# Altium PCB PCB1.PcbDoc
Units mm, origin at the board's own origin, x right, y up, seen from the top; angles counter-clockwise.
Board outline 100 x 140 mm, 2 copper layers (Top Layer, Bottom Layer); 119 components, 80 nets, 399 pads, 0 vias.
Unrouted connection lines stored in the file: 245.
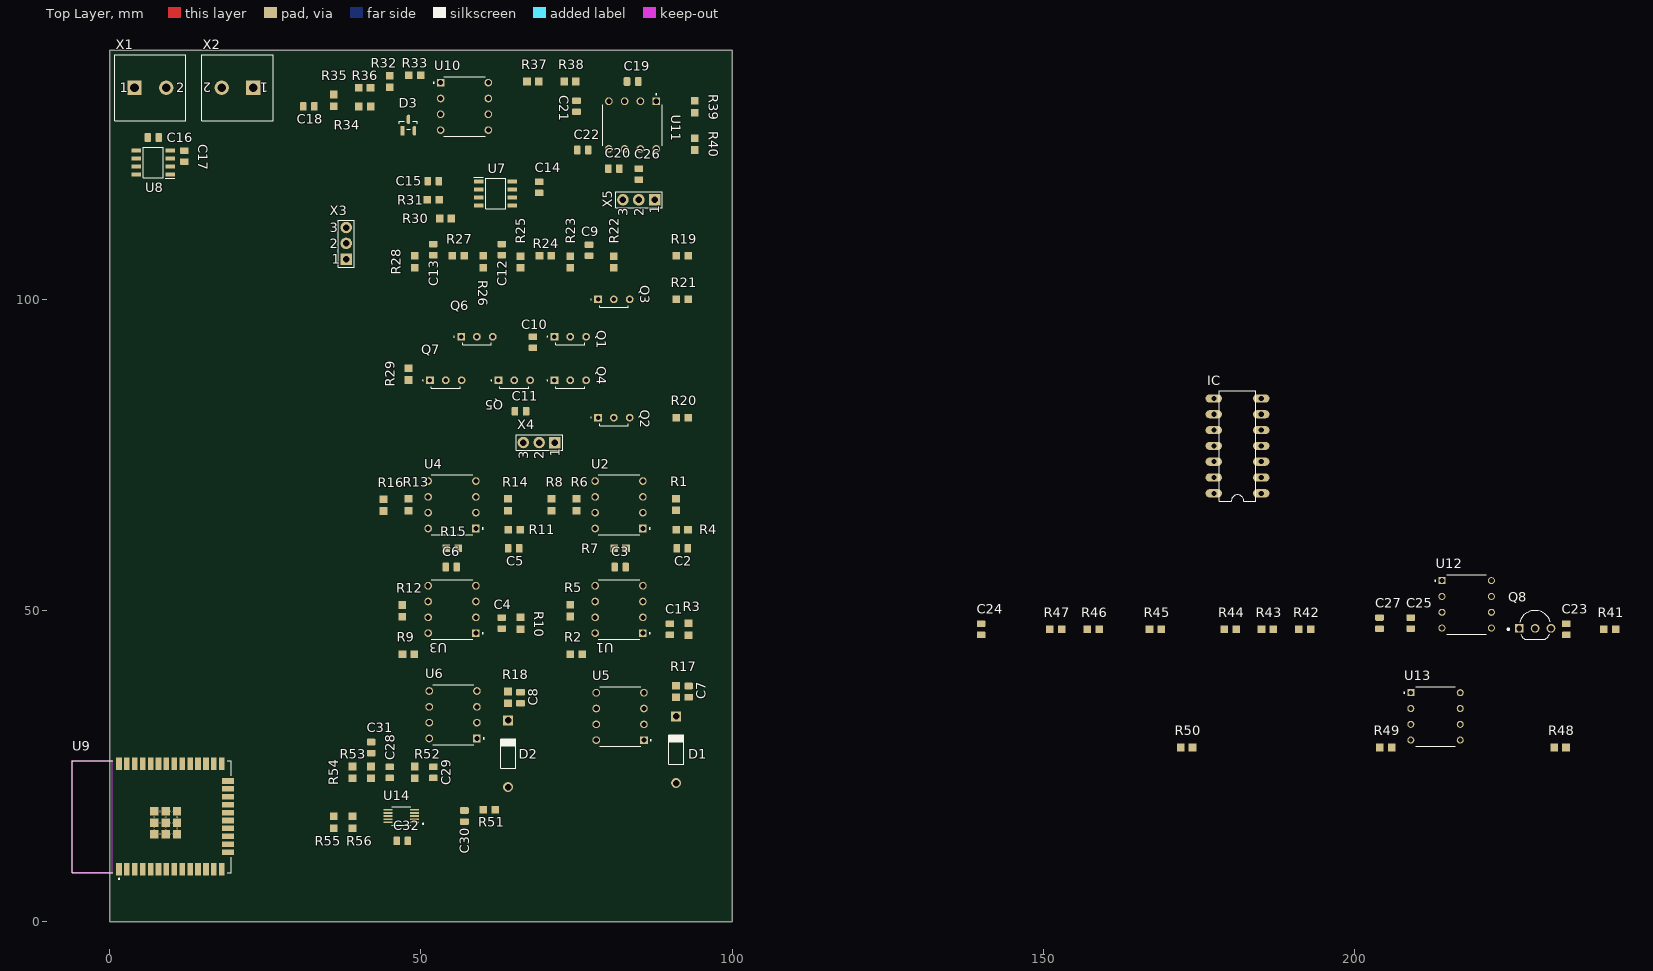
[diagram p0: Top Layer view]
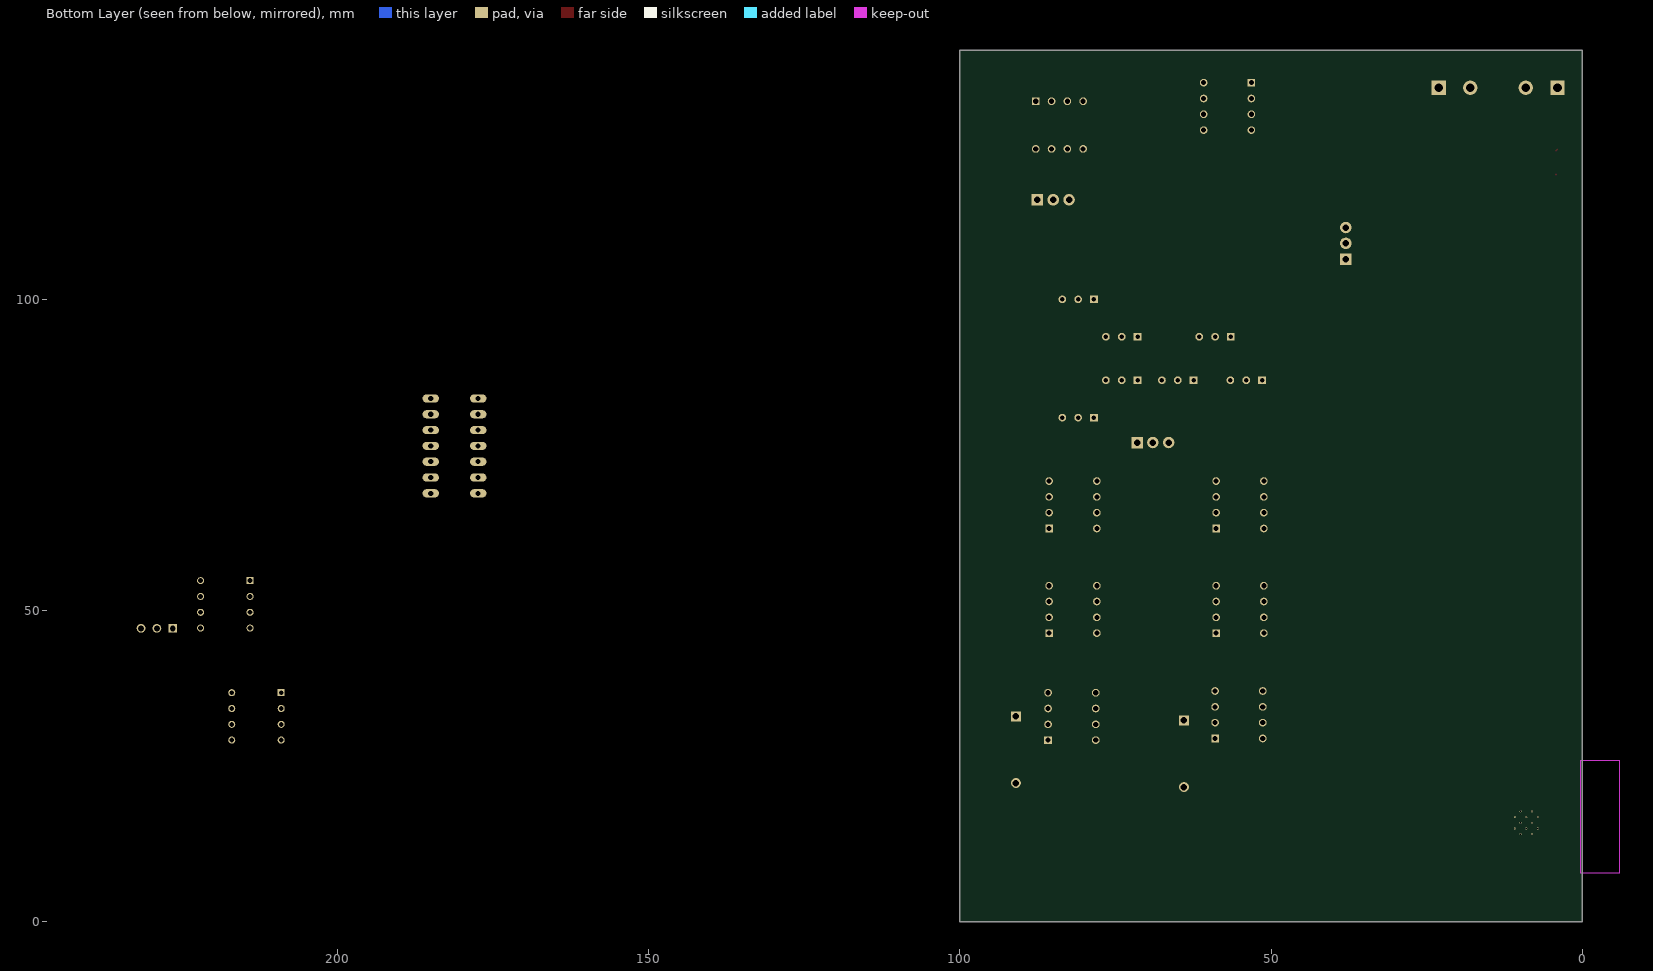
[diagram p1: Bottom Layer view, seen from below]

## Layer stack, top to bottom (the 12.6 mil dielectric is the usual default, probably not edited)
Top Solder: solder mask 0.0102, Solder Resist, Dk 3.5
Top Layer: signal copper 0.0356
Dielectric 1: dielectric 0.32, FR-4, Dk 4.8
Bottom Layer: signal copper 0.0356
Bottom Solder: solder mask 0.0102, Solder Resist, Dk 3.5

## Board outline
0,0 100,0 100,140 0,140

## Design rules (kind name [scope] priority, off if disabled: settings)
Clearance [All] p1: gap=0.254 ignorepadtopadclearanceinfootprint=FALSE
PolygonConnect [All] p1: connectstyle=Relief reliefconductorwidth=0.254 reliefentries=4 polygonreliefangle="90 Angle" airgapwidth=0.254
RoutingVias [All] p1: holewidth=0.711 width=1.27 viastyle="Through Hole" minholewidth=0.711 minwidth=1.27 maxholewidth=0.711 maxwidth=1.27
SolderMaskExpansion [All] p1: expansion=0 istentingtop=FALSE
SupplyNets "Schematic Supply Nets" [InNet('GND')] p1: voltage=0.000
Width [All] p1: maxlimit=0.254 minlimit=0.254 preferedwidth=0.254
30 further rules are at their usual default settings.

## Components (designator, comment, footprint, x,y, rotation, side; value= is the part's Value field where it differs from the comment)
C1 "100nF" CAPC2012X95N 90,47 r90 top
C2 "100nF" CAPC2012X95N 92,60 r180 top
C3 "100nF" CAPC2012X95N 82,57 r0 top
C4 "100nF" CAPC2012X95N 63,48 r90 top
C5 "100nF" CAPC2012X95N 64.888,60 r180 top
C6 "100nF" CAPC2012X95N 54.888,57 r180 top
C7 "100nF" CAPC2012X95N 93,37 r90 top
C8 "100nF" CAPC2012X95N 66,36 r90 top
C9 "100nF" CAPC2012X95N 77,107.888 r90 top
C10 "100nF" CAPC2012X95N 68,93.112 r270 top
C11 "100nF" CAPC2012X95N 66,82 r180 top
C12 "100nF" CAPC2012X95N 63,108 r90 top
C13 "100nF" CAPC2012X95N 52,108 r90 top
C14 "100nF" CAPC2012X95N 69,118 r270 top
C15 "100nF" CAPC2012X95N 52,119 r0 top
C16 "100nF" CAPC2012X95N 7,126 r0 top
C17 "100nF" CAPC2012X95N 12,123 r90 top
C18 "1nF" CAPC2012X95N 32,131 r180 top
C19 "1.2nF" CAPC2012X95N 84,135 r0 top
C20 "6.8nF" CAPC2012X95N 81,121 r0 top
C21 "1nF" CAPC2012X95N 75,131 r90 top
C22 "1nF" CAPC2012X95N 76,124 r0 top
C23 "100nF" CAPC2012X95N 234,47 r90 top
C24 "100nF" CAPC2012X95N 140,47 r90 top
C25 "100nF" CAPC2012X95N 209,48 r90 top
C26 "100nF" CAPC2012X95N 85,120.112 r90 top
C27 "100nF" CAPC2012X95N 204,48 r90 top
C28 "100pF" CAPC2012X95N 45,24 r90 top value=1nF
C29 "100pF" CAPC2012X95N 52,24 r90 top value=1nF
C30 "100pF" CAPC2012X95N 57,17 r270 top value=1nF
C31 "100nF" CAPC2012X95N 42,28 r270 top value=1nF
C32 "100nF" CAPC2012X95N 47,13 r180 top value=1nF
D1 "IN4007" DIOAD1070W78L470D235P 91,27.65 r270 top
D2 "IN4007" DIOAD1070W78L470D235P 64,27 r270 top
D3 "BAV99LT1G" FP-318-08-IPC_B 48,128 r90 top
IC "ICL8038" ICL8038 181.19,76.46 r90 top
Q1 "2N2222A" 2N2222A 71.46,94 r0 top
Q2 "2N2222A" 2N2222A 78.46,81 r0 top
Q3 "2N2222A" 2N2222A 78.46,100 r0 top
Q4 "2N2222A" 2N2222A 71.46,87 r0 top
Q5 "2N2222A" 2N2222A 62.46,87 r0 top
Q6 "2N2222A" 2N2222A 56.46,94 r0 top
Q7 "2N2222A" 2N2222A 51.46,87 r0 top
Q8 "2N3904TF" TO92254P520H877-3 229,48 r0 top
R1 "10k" RC0805N_YAG-M 91,67.048 r90 top
R2 "10k" RC0805N_YAG-M 74.953,43 r0 top
R3 "10k" RC0805N_YAG-M 93,47 r90 top
R4 "10k" RC0805N_YAG-M 91.953,63 r0 top
R5 "10k" RC0805N_YAG-M 74,50 r90 top
R6 "10k" RC0805N_YAG-M 75,67 r90 top
R7 "10k" RC0805N_YAG-M 82,60 r0 top
R8 "10k" RC0805N_YAG-M 71,67 r270 top
R9 "10k" RC0805N_YAG-M 48,43 r0 top
R10 "10k" RC0805N_YAG-M 66,47.953 r270 top
R11 "10k" RC0805N_YAG-M 65,63 r0 top
R12 "10k" RC0805N_YAG-M 47,49.953 r90 top
R13 "10k" RC0805N_YAG-M 48,67 r90 top
R14 "10k" RC0805N_YAG-M 64,67 r90 top
R15 "10k" RC0805N_YAG-M 55.048,60 r0 top
R16 "10k" RC0805N_YAG-M 44,66.953 r270 top
R17 "10k" RC0805N_YAG-M 91,37 r270 top
R18 "10k" RC0805N_YAG-M 64,36.048 r270 top
R19 "10k" RC0805N_YAG-M 92,107 r0 top
R20 "10k" RC0805N_YAG-M 92,81 r0 top
R21 "10k" RC0805N_YAG-M 92,100 r0 top
R22 "10k" RC0805N_YAG-M 81,106 r270 top
R23 "10k" RC0805N_YAG-M 74,106 r270 top
R24 "10k" RC0805N_YAG-M 70,107 r0 top
R25 "10k" RC0805N_YAG-M 66,106 r270 top
R26 "10k" RC0805N_YAG-M 60,106.048 r270 top
R27 "10k" RC0805N_YAG-M 56,107 r0 top
R28 "10k" RC0805N_YAG-M 49,106.048 r90 top
R29 "10k" RC0805N_YAG-M 48,88 r270 top
R30 "10k" RC0805N_YAG-M 53.953,113 r180 top
R31 "10k" RC0805N_YAG-M 52,116 r180 top
R32 "25k" RC0805N_YAG-M 45,135 r270 top
R33 "2.8k" RC0805N_YAG-M 49,136 r180 top
R34 "47.5k" RC0805N_YAG-M 41,131 r180 top
R35 "10M" RC0805N_YAG-M 36,131.953 r90 top
R36 "909" RC0805N_YAG-M 40.953,134 r180 top
R37 "29.4k" RC0805N_YAG-M 68,135 r180 top
R38 "29.4k" RC0805N_YAG-M 73.953,135 r180 top
R39 "12.4k" RC0805N_YAG-M 94,130.953 r90 top
R40 "12.4k" RC0805N_YAG-M 94,124.953 r90 top
R41 "10k" RC0805N_YAG-M 241,47 r0 top
R42 "10k" RC0805N_YAG-M 192,47 r0 top
R43 "10k" RC0805N_YAG-M 186,47 r0 top
R44 "10k" RC0805N_YAG-M 180,47 r0 top
R45 "10k" RC0805N_YAG-M 168,47 r0 top
R46 "10k" RC0805N_YAG-M 158,47 r0 top
R47 "10k" RC0805N_YAG-M 152,47 r0 top
R48 "10k" RC0805N_YAG-M 233,28 r0 top
R49 "10k" RC0805N_YAG-M 205,28 r0 top
R50 "10k" RC0805N_YAG-M 173,28 r0 top
R51 "1k" RC0805N_YAG-M 61,18 r0 top value=10k
R52 "1k" RC0805N_YAG-M 49,24 r90 top value=10k
R53 "1k" RC0805N_YAG-M 42,24 r90 top value=10k
R54 "10k" RC0805N_YAG-M 39,24 r90 top
R55 "4.7k" RC0805N_YAG-M 36,16 r90 top value=10k
R56 "4.7k" RC0805N_YAG-M 39,16 r90 top value=10k
U1 "NE5532N" DIP766W45P254L1016H533Q8 81.83,50.19 r180 top
U2 "NE5532N" DIP766W45P254L1016H533Q8 81.83,67 r180 top
U3 "NE5532N" DIP766W45P254L1016H533Q8 55,50.19 r180 top
U4 "NE5532N" DIP766W45P254L1016H533Q8 55,67 r180 top
U5 "NE5532N" DIP766W45P254L1016H533Q8 82,33 r180 top
U6 "NE5532N" DIP766W45P254L1016H533Q8 55.17,33.27 r180 top
U7 "AD633JRZ-R7" SOIC127P600X175-8N 62,117 r0 top
U8 "ICL7660SIBAZT" SOIC127P600X175-8N 7,122 r180 top
U9 "ESP32-WROOM-32D-N4" MODULE_ESP32-WROOM-32D-N4 6.76,16.917 r90 top
U10 "NE5532N" DIP766W45P254L1016H533Q8 57,131 r0 top
U11 "NE5532N" DIP766W45P254L1016H533Q8 84,128 r270 top
U12 "TL072CPE4" DIP794W45P254L959H508Q8 218,51 r0 top
U13 "TL072CPE4" DIP794W45P254L959H508Q8 213,33 r0 top
U14 "ADS1115IDGSR" SOP50P490X110-10N 46.85,17 r180 top
X1 "Terminal" CON_TERMINAL_2POL 4,134 r0 top value=10k
X2 "Terminal" CON_TERMINAL_2POL 23.08,134 r180 top value=10k
X3 "Jumper" CON_JUMPER_3POL 38,106.46 r0 top value=10k
X4 "Jumper" CON_JUMPER_3POL 71.54,77 r90 top value=10k
X5 "Jumper" CON_JUMPER_3POL 87.54,116 r90 top value=10k

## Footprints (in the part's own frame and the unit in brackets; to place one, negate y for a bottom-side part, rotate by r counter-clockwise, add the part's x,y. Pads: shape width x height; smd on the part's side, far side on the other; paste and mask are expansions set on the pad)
2N2222A [mm]
  rect 1.234x1.234 hole 0.72: 1(0,0)
  round 1.234 hole 0.72: 2(2.54,0) 3(5.08,0)
  silkscreen extent -1.2,-1.27 4.84,0.05, body extent -0.2,-1.25 5.28,2.35, height 7.46
CAPC2012X95N [mm]
  rrect25% 1.05x1.38 smd: 1(-0.888,0) 2(0.888,0)
  body extent -1,-0.63 1,0.63, height 0.95
CON_JUMPER_3POL [mm] "Jumper"
  rect 1.85x1.85 hole 1.05: 1(0,0)
  round 1.85 hole 1.05: 2(0,2.54) 2(0,5.08)
  silkscreen extent -1.27,-1.27 1.27,6.22
CON_TERMINAL_2POL [mm] "Terminal Screw"
  rect 2.3x2.3 hole 1.4: 1(0,0)
  round 2.3 hole 1.4: 2(5.08,0)
  silkscreen extent -3.17,-5.33 8.25,5.33
DIOAD1070W78L470D235P [mm]
  round 1.6 hole 1.05: A(5.35,0)
  rect 1.6x1.6 / inner round 1.6 / far side rect 1.6x1.6 hole 1.05: C(-5.35,0)
  silkscreen extent -2.4,-1.2 2.35,1.2, body extent -5.74,-1.35 5.74,1.35, height 2.7
DIP766W45P254L1016H533Q8 [mm]
  rect 1.23x1.23 / inner round 1.23 / far side rect 1.23x1.23 hole 0.82: 1(-3.83,3.81)
  round 1.23 hole 0.82: 2(-3.83,1.27) 3(-3.83,-1.27) 4(-3.83,-3.81) 5(3.83,-3.81) 6(3.83,-1.27) 7(3.83,1.27) 8(3.83,3.81)
  silkscreen extent -5.03,-4.79 3.3,4.79, body extent -4,-4.94 4,4.94, height 5.33
DIP794W45P254L959H508Q8 [mm]
  rect 1.13x1.13 / inner round 1.13 / far side rect 1.13x1.13 hole 0.78 mask+0.102: 1(-3.97,3.81)
  round 1.13 hole 0.78 mask+0.102: 2(-3.97,1.27) 3(-3.97,-1.27) 4(-3.97,-3.81) 5(3.97,-3.81) 6(3.97,-1.27) 7(3.97,1.27) 8(3.97,3.81)
  silkscreen extent -5.13,-4.79 3.17,4.79, body extent -4.1,-4.79 4.1,4.79, height 5.08
FP-318-08-IPC_B [mm]
  rect 1.524x0.578 smd paste+0 mask+0: 1(-0.91,0.95)
  rrect100% 1.524x0.578 smd paste+0 mask+0: 2(-0.91,-0.95) 3(0.91,0)
  silkscreen extent -0.65,-1.45 0.65,1.45, body extent -1.92,-1.7 1.92,1.7, height 0.25
ICL8038 [mil]
  oval 52x104 hole 32: 1(-300,-150) 2(-200,-150) 3(-100,-150) 4(0,-150) 5(100,-150) 6(200,-150) 7(300,-150) 8(300,150) 9(200,150) 10(100,150) 11(0,150) 12(-100,150) 13(-200,150) 14(-300,150)
  silkscreen extent -350,-115 350,115
MODULE_ESP32-WROOM-32D-N4 [mm]
  rect 2x0.9 smd: 1(-8.5,5.26) 2(-8.5,3.99) 3(-8.5,2.72) 4(-8.5,1.45) 5(-8.5,0.18) 6(-8.5,-1.09) 7(-8.5,-2.36) 8(-8.5,-3.63) 9(-8.5,-4.9) 10(-8.5,-6.17) 11(-8.5,-7.44) 12(-8.5,-8.71) 13(-8.5,-9.98) 14(-8.5,-11.25) 25(8.5,-11.25) 26(8.5,-9.98) 27(8.5,-8.71) 28(8.5,-7.44) 29(8.5,-6.17) 30(8.5,-4.9) 31(8.5,-3.63) 32(8.5,-2.36) 33(8.5,-1.09) 34(8.5,0.18) 35(8.5,1.45) 36(8.5,2.72) 37(8.5,3.99) 38(8.5,5.26)
  rect 0.9x2 smd: 15(-5.715,-12.25) 16(-4.445,-12.25) 17(-3.175,-12.25) 18(-1.905,-12.25) 19(-0.635,-12.25) 20(0.635,-12.25) 21(1.905,-12.25) 22(3.175,-12.25) 23(4.445,-12.25) 24(5.715,-12.25)
  rect 1.33x1.33 smd: 39_1(-2.835,-0.405) 39_2(-1,-0.405) 39_3(0.835,-0.405) 39_4(-2.835,-2.24) 39_5(-1,-2.24) 39_6(0.835,-2.24) 39_7(-2.835,-4.075) 39_8(-1,-4.075) 39_9(0.835,-4.075)
  round 0.3 hole 0.2: 39_10(-1.917,-0.405) 39_11(-0.082,-0.405) 39_12(-2.835,-1.322) 39_13(-1,-1.322) 39_14(0.835,-1.322) 39_15(-1.917,-2.24) 39_16(-0.082,-2.24) 39_17(-2.835,-3.157) 39_18(-1,-3.157) 39_19(0.835,-3.157) 39_20(-1.917,-4.075) 39_21(-0.082,-4.075)
  Keep-Out Layer region: 9,6.45 -9,6.45 -9,12.75 9,12.75
  silkscreen extent -10.1,-12.75 9,12.75, body extent -9,-12.75 9,12.75, height 3.25
RC0805N_YAG-M [mil]
  rect 48x49 smd paste+0 mask+0: 1(-37.5,0) 2(37.5,0)
  body extent -39,-24 39,24, height 28
SOIC127P600X175-8N [mm]
  rect 1.525x0.65 smd: 1(-2.712,1.905) 2(-2.712,0.635) 3(-2.712,-0.635) 4(-2.712,-1.905) 5(2.712,-1.905) 6(2.712,-0.635) 7(2.712,0.635) 8(2.712,1.905)
  silkscreen extent -3.47,-2.45 1.6,2.58, body extent -3,-2.45 3,2.45, height 1.75
SOP50P490X110-10N [mm]
  rrect25% 1.47x0.28 smd: 1(-2.15,1) 2(-2.15,0.5) 3(-2.15,0) 4(-2.15,-0.5) 5(-2.15,-1) 6(2.15,-1) 7(2.15,-0.5) 8(2.15,0) 9(2.15,0.5) 10(2.15,1)
  silkscreen extent -3.6,-1.5 1.5,1.5, body extent -2.45,-1.5 2.45,1.5, height 1.1
TO92254P520H877-3 [mm]
  rect 1.41x1.41 / inner round 1.41 / far side rect 1.41x1.41 hole 0.94: 1(-2.54,-0.853)
  round 1.41 hole 0.94: 2(0,-0.853) 3(2.54,-0.853)
  silkscreen extent -4.44,-2.62 2.47,2.01, body extent -2.83,-1.43 2.83,2.19, height 8.77

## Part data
C1 C2 C3 C4 C5 C6 C7 C8 C9 C10 C11 C12 C13 C14 C15 C16 C17 C18 C19 C20 C21 C22 C23 C24 C25 C26 C27 C28 C29 C30 C31 C32: library part CAP_0805_GENERIC, "0.1 ÂµF Â±10% 50V Ceramic Capacitor X7R 0805 (2012 Metric)", Package="SMD-2 Samsung", Voltage=50V
D1 D2: "Diode Standard 1000 V 1A Through Hole DO-204AL (DO-41)", Package="DO-41 Vishay Semiconductor"
D3: library part CMP-07163-000036-1, "DIODE ARRAY 100V 215MA SOT23-3", Capacitance=1.5pF, Case/Package=SOT-23, Current Rating=200mA, Forward Current=150mA, Forward Voltage=1.25V, Max Forward Surge Current (Ifsm)=500mA, Max Operating Temperature=150°C, Max Repetitive Reverse Voltage (Vrrm)=70V, Min Operating Temperature=-65°C, Peak Non-Repetitive Surge Current=2A, Peak Reverse Current=2.5uA
IC: "IC OSCILL GEN/VOLT CONTROL 14DIP", Package=None
Q1 Q2 Q3 Q4 Q5 Q6 Q7: "Transistor BJT NPN", Manufacturer_Name=Diotec, Mouser Part Number=637-2N2222A
Q8: "Transistor General Purpose BJT NPN 40 Volt 0.2 Amp 3-Pin TO-92 Tape And Reel", Package="TO-92-3 ON Semiconductor"
R1 R2 R3 R4 R5 R6 R7 R8 R9 R10 R11 R12 R13 R14 R15 R16 R17 R18 R19 R20 R21 R22 R23 R24 R25 R26 R27 R28 R29 R30 R31 R32 R33 R34 R35 R36 R37 R38 R39 R40 R41 R42 R43 R44 R45 R46 R47 R48 R49 R50 R51 R52 R53 R54 R55 R56: library part RES_0805_GENERIC_1, "Description", Manufacturer_Name=Yageo, Manufacturer_Part_Number=RC0805FR-0710KL
U1 U2 U3 U4 U5 U6 U10 U11: "IC, OP AMP, DUAL; No. of Amplifiers: 2 Amplifier; Bandwidth: 10MHz; Slew Rate: 8V/Âµs; Supply Voltage Range: Â± 15V; Amplifier Case Style: DIP; No. of Pins: 8Pins; Operating Temperature Min: 0Â°C; Operating Temperature Max: 70Â°C; MSL: -; SVHC: No SVHC (1", Package="PDIP-8 ON Semiconductor"
U7: "Analog Multiplier 4-Quadrant 8-SOIC", Package="SOIC-8 Analog Devices"
U8: "Charge Pump Switching Regulator IC Positive or Negative Fixed -Vin, 2Vin 1 Output 45mA 8-SOIC (0.154, 3.90mm Width)", Package="SOIC-8 Renesas Electronics America Inc"
U9: "Bluetooth, WiFi 802.11b/g/n, Bluetooth v4.2 +EDR, Class 1, 2 and 3 Transceiver Module 2.4GHz ~ 2.5GHz Integrated, Trace Surface Mount", Package="Non Standard Espressif Systems"
U12 U13: "Dual Low-Noise JFET-Input General-Purpose Operational Amplifier 8-PDIP 0 to 70", Package="PDIP-8 Texas"
U14: "16-bit, 860-SPS, 4-channel, delta-sigma ADC with PGA, oscillator, VREF, comparator and I2C", Package="VSSOP-10 Texas Instruments"
X1 X2: library part CON_TERMINAL_2POL, "Terminal Screw", Manufacturer_Name=Yageo, Manufacturer_Part_Number=RC0805FR-0710KL
X3 X4 X5: library part CON_JUMPER_3POL, Manufacturer_Name=Yageo, Manufacturer_Part_Number=RC0805FR-0710KL

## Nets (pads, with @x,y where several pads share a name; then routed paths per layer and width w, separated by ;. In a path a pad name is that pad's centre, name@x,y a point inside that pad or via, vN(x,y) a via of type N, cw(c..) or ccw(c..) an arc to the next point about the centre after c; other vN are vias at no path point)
GND: C7.2 C8.2 C9.2 C10.1 C11.1 C12.2 C13.2 C14.1 C15.1 C16.2 C21.1 C22.1 C28.2 C29.2 C30.2 C32.1 R17.1 R18.1 R28.1 R29.1 R31.2 R35.2 R36.2 R54.2 U1.3 U1.5 U2.3 U2.5 U3.3 U3.5 U4.3 U4.5 U7.2 U7.8 U8.3 U13.3 U14.1 U14.3 X1.2 X2.2
NetC1_1: C1.1 R3.1 U1.1
NetC1_2: C1.2 R2.2 U1.2
NetC2_1: C2.1 R1.1 R3.2 R4.2 U2.2
NetC2_2: C2.2 C3.1 R4.1 R7.2 U2.1
NetC3_2: C3.2 R5.2 R7.1 U1.6
NetC4_1: C4.1 R10.1 U3.1
NetC4_2: C4.2 R9.2 U3.2
NetC5_1: C5.1 R10.2 R11.2 R14.1 U4.2
NetC5_2: C5.2 C6.1 R11.1 R15.2 U4.1
NetC6_2: C6.2 R12.2 R15.1 U3.6
NetC7_1: C7.1 D1.C R17.2 U5.2 U5.5
NetC8_1: C8.1 D2.C R18.2 U6.2 U6.5
NetC9_1: C9.1 R19.1 R22.1 R23.1 R24.2
NetC10_2: C10.2 Q1.2 Q4.2 R23.2
NetC11_2: C11.2 Q5.2 R25.2
NetC12_1: C12.1 R24.1 R25.1 R26.1 R27.2
NetC13_1: C13.1 Q7.2 R27.1 R28.2
NetC14_2: C14.2 C32.2 D3.2 IC.6 R19.2 R20.2 R21.2 R45.2 R47.2 R55.2 R56.2 U1.8 U2.8 U3.8 U4.8 U5.8 U6.8 U7.6 U8.8 U10.8 U11.8 U12.8 U13.8 U14.8 X1.1 | length 0.1
  Top Layer w0.254: U8.8@4.193,120 U8.8
NetC15_2: C15.2 C16.1 C24.2 D3.1 IC.11 R46.1 R50.1 U1.4 U2.4 U3.4 U4.4 U5.4 U6.4 U7.3 U8.5 U10.4 U11.4 U12.4 U13.4 | length 0.4
  Top Layer w0.254: U8.5@4,124.103 4.198,123.905 U8.5
NetC17_1: C17.1 U8.2
NetC17_2: C17.2 U8.4
NetC18_1: C18.1 R34.2 R35.1
NetC18_2: C18.2 X2.1
NetC19_1: C19.1 C21.2 R38.1 U11.3
NetC19_2: C19.2 R39.2 U11.1 U11.2
NetC20_1: C20.1 C22.2 R40.1 U11.5
NetC20_2: C20.2 C26.2 U11.6 U11.7
NetC23_1: C23.1 Q8.1 R42.1 U12.2
NetC23_2: C23.2 C31.1 IC.8 Q8.3 R44.1 U12.1
NetC24_1: C24.1 IC.10
NetC25_1: C25.1 X3.2
NetC25_2: C25.2 R48.1 U13.1
NetC26_1: C26.1 X5.2
NetC27_1: C27.1 X4.2
NetC27_2: C27.2 R1.2 R14.2
NetC28_1: C28.1 R53.1 U14.6
NetC29_1: C29.1 R52.1 U14.5
NetC30_1: C30.1 R51.1 U14.4
NetC31_2: C31.2 R53.2
NetD1_A: D1.A U5.1
NetD2_A: D2.A U6.1
NetD3_3: D3.3 R34.1 U10.3
NetIC_3: IC.3 R49.2
NetIC_4: IC.4 R45.1
NetIC_5: IC.5 R47.1
NetIC_12: IC.12 R46.2
NetQ1_1: Q1.1 Q3.1 Q6.3
NetQ1_3: Q1.3 Q2.3 R20.1 X4.1
NetQ2_1: Q2.1 Q4.1 Q5.3
NetQ2_2: Q2.2 Q3.2 R22.2 X5.1
NetQ3_3: Q3.3 Q4.3 R21.1
NetQ5_1: Q5.1 Q6.1 Q7.3
NetQ6_2: Q6.2 R26.2 X3.1
NetQ7_1: Q7.1 R29.2
NetQ8_2: Q8.2 R41.2
NetR2_1: R2.1 R5.1 R8.2 U1.7
NetR6_1: R6.1 U2.7 U5.3
NetR6_2: R6.2 R8.1 U2.6
NetR9_1: R9.1 R12.1 R16.2 U3.7
NetR13_1: R13.1 U4.7 U6.3
NetR13_2: R13.2 R16.1 U4.6
NetR30_1: R30.1 U7.5
NetR30_2: R30.2 R31.1 U7.4
NetR32_1: R32.1 R33.2
NetR32_2: R32.2 R36.1 U10.2
NetR33_1: R33.1 R37.2 U10.1
NetR37_1: R37.1 R38.2
NetR39_1: R39.1 R40.2
NetR41_1: R41.1 R43.1 U12.7
NetR42_2: R42.2 U12.6
NetR43_2: R43.2 R44.2 U12.5
NetR48_2: R48.2 R49.1 R50.2 U13.2
NetR51_2: R51.2 U5.6 U5.7
NetR52_2: R52.2 U6.6 U6.7
NetR54_1: R54.1 U14.7
NetR55_1: R55.1 U9.36 U14.10
NetR56_1: R56.1 U9.33 U14.9
NetU7_1: U7.1
NetU7_7: U7.7
pads on no net: IC.1 IC.2 IC.7 IC.9 IC.13 IC.14 U8.1 U8.6 U8.7 U9.1 U9.2 U9.3 U9.4 U9.5 U9.6 U9.7 U9.8 U9.9 U9.10 U9.11 U9.12 U9.13 U9.14 U9.15 U9.16 U9.17 U9.18 U9.19 U9.20 U9.21 U9.22 U9.23 U9.24 U9.25 U9.26 U9.27 U9.28 U9.29 U9.30 U9.31 U9.32 U9.34 U9.35 U9.37 U9.38 U9.39_1 U9.39_2 U9.39_3 U9.39_4 U9.39_5 U9.39_6 U9.39_7 U9.39_8 U9.39_9 U9.39_10 U9.39_11 U9.39_12 U9.39_13 U9.39_14 U9.39_15 U9.39_16 U9.39_17 U9.39_18 U9.39_19 U9.39_20 U9.39_21 U10.5 U10.6 U10.7 U12.3 U13.5 U13.6 U13.7 U14.2

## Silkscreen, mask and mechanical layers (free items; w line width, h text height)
Mechanical 1:
  lines w0.2: 100,0 0,0 0,140 25,140 75,140 100,140 100,0 ; 100,0 100,0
